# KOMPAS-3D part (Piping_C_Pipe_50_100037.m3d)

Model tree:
1. Plane XY
2. Plane ZX
3. Plane ZY
4. X Axis
5. Y Axis
6. Z Axis
7. Origin
8. Path  (labels: Отвод 90 Dy 50; Труба Dy 50)
9. Plane of section
10. Section of pipe
11. Pipe
     Толщина стенки 1 = 1

Referenced files in C:\Program Files\ASCON\KOMPAS-3D V10\Libs\Piping\Models\Tanks\: Tanks.a3d
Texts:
  Pipe Dn 50
  Three Point Plane
  Plane at Angle
  Line and Point Plane
  Axis through Two Vertices
  Axis of Feature
  Axis of Conical Surface
  Axis through Edge
  Приклеить элемент выдавливания
  Приклеить элемент вращения
  Приклеить кинематический элемент
  Приклеить элемент по сечениям
  Trim by Surface
  Trim by Sketch
  Feature with No History
  Intersection Axis of Two Planes
  Two Line Plane
  Line and Face Plane
  Bend by line
  Hole in sheet body
  Cut in sheet body
  Point in CM
  Linear Dimension from Line to Point
  Surface Finish Symbol
  Geometric Tolerance Symbol
  Текст на чертеже
  Линия-выноска #1
  Линия-выноска #2
  Линия-выноска #3
  Отклонения формы и база
  Марка координационной оси
  Марка/позиционное обозначение с линией-выноской
  Марка/позиционное обозначение на линии
  Марка/позиционное обозначение без линии-выноски
  Отвод 90 Dy 50
  Труба Dy 50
